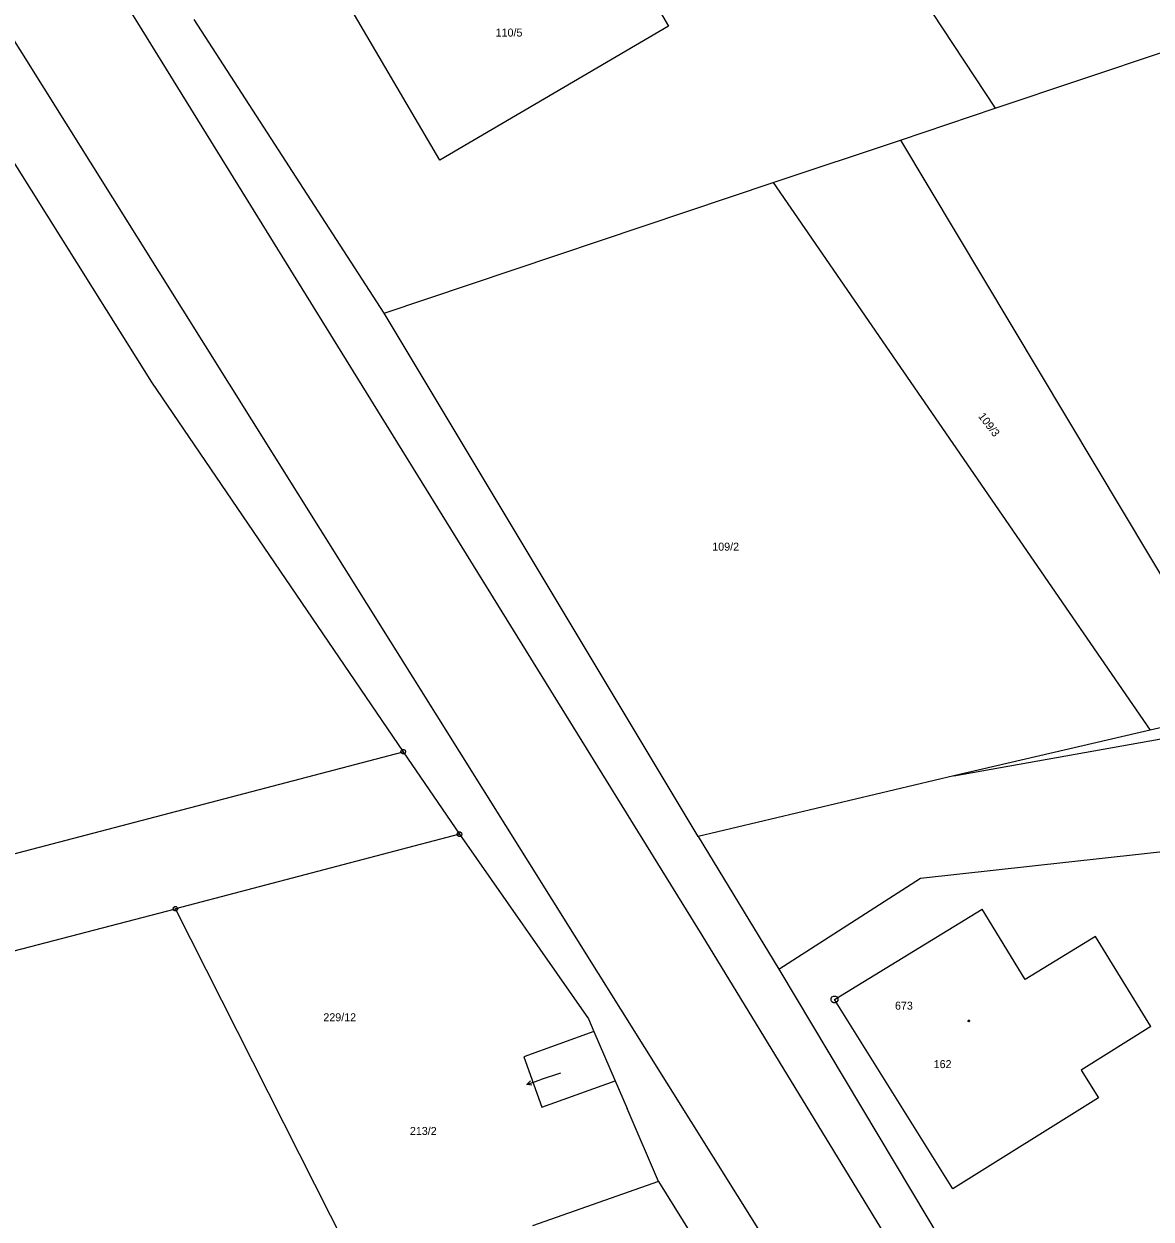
# Model space of a CAD drawing. Extents: x -871430 to -870620, y -1010094 to -1009649.
# Drawn here: x -871056.6 to -870996.8, y -1009857 to -1009793.5 of the extents above; entities that cross this region are included whole.
import ezdxf

# ---------------------------------------------------------------- set-up
doc = ezdxf.new("R2010")
doc.units = 0
for name, color, linetype in [('Vrstva 1', 7, 'Continuous'), ('Vrstva 2', 7, 'Continuous'), ('Vrstva 4', 7, 'Continuous'), ('Vrstva 5', 7, 'Continuous'), ('Vrstva 7', 7, 'Continuous'), ('Vrstva 8', 7, 'Continuous')]:
    doc.layers.add(name, color=color, linetype=linetype)

msp = doc.modelspace()

# ---------------------------------------------------------------- linework, layer by layer
at = {"layer": 'Vrstva 1'}
for p, q in [((-871019.06, -1009776.69), (-871005.04, -1009798.01)), ((-871037.49, -1009808.89), (-871047.58, -1009793.3)), ((-871005.04, -1009798.01), (-870995.93, -1009794.96)), ((-871010.06, -1009799.7), (-871005.04, -1009798.01)), ((-871057.82, -1009799.84), (-871049.86, -1009812.56)), ((-871016.82, -1009801.96), (-871010.06, -1009799.7)), ((-871010.06, -1009799.7), (-870991.98, -1009829.94)), ((-871037.49, -1009808.89), (-871016.82, -1009801.96)), ((-871016.82, -1009801.96), (-870996.8, -1009831.05)), ((-871020.82, -1009836.7), (-871037.49, -1009808.89)), ((-871049.86, -1009812.56), (-871036.48, -1009832.19)), ((-870991.98, -1009829.94), (-870996.8, -1009831.05)), ((-871007.23, -1009833.47), (-870991.55, -1009830.67)), ((-870996.8, -1009831.05), (-871007.23, -1009833.47)), ((-871091.79, -1009846.7), (-871036.48, -1009832.19)), ((-871036.48, -1009832.19), (-871033.49, -1009836.57)), ((-871007.23, -1009833.47), (-871020.82, -1009836.7)), ((-871033.49, -1009836.57), (-871048.58, -1009840.53)), ((-871033.49, -1009836.57), (-871026.64, -1009846.38)), ((-871020.82, -1009836.7), (-871016.52, -1009843.75)), ((-871009.01, -1009838.9), (-870993.95, -1009837.25)), ((-871016.52, -1009843.75), (-871009.01, -1009838.9)), ((-871131.99, -1009862.23), (-871048.58, -1009840.53)), ((-871038.84, -1009859.8), (-871048.58, -1009840.53)), ((-871013.57, -1009845.35), (-871005.72, -1009840.56)), ((-871003.45, -1009844.29), (-871005.72, -1009840.56)), ((-870999.7, -1009842), (-871003.45, -1009844.29)), ((-870996.77, -1009846.79), (-870999.7, -1009842)), ((-871016.52, -1009843.75), (-871002.66, -1009866.96)), ((-871007.28, -1009855.41), (-871013.57, -1009845.35)), ((-871026.64, -1009846.38), (-871026.35, -1009847.05)), ((-870996.77, -1009846.79), (-871000.47, -1009849.1)), ((-871026.35, -1009847.05), (-871030.08, -1009848.4)), ((-871026.35, -1009847.05), (-871025.22, -1009849.67)), ((-871030.08, -1009848.4), (-871029.11, -1009851.08)), ((-871000.47, -1009849.1), (-870999.55, -1009850.58)), ((-871029.11, -1009851.08), (-871025.22, -1009849.67)), ((-871025.22, -1009849.67), (-871024.58, -1009851.15)), ((-870999.55, -1009850.58), (-871007.28, -1009855.41)), ((-871022.92, -1009855.02), (-871024.58, -1009851.15)), ((-871022.92, -1009855.02), (-871029.61, -1009857.37)), ((-871022.92, -1009855.02), (-871009.29, -1009876.82))]:
    msp.add_line(p, q, dxfattribs=at)
msp.add_lwpolyline([(-871039.55, -1009792.22), (-871027.38, -1009785.1), (-871022.38, -1009793.65), (-871034.54, -1009800.76), (-871039.55, -1009792.22)], dxfattribs=at)
at = {"layer": 'Vrstva 4'}
for p, q in [((-871086.33, -1009747.82), (-871017.56, -1009857.66)), ((-871020.6, -1009841.94), (-871072.78, -1009757.54)), ((-870955.86, -1009947.84), (-871020.6, -1009841.94))]:
    msp.add_line(p, q, dxfattribs=at)
at = {"layer": 'Vrstva 5'}
msp.add_lwpolyline([(-871006.44, -1009846.448), (-871006.415, -1009846.452), (-871006.402, -1009846.475), (-871006.398, -1009846.49), (-871006.402, -1009846.512), (-871006.422, -1009846.53), (-871006.44, -1009846.532), (-871006.462, -1009846.525), (-871006.477, -1009846.51), (-871006.482, -1009846.49), (-871006.477, -1009846.468), (-871006.457, -1009846.45), (-871006.44, -1009846.448)], dxfattribs=at)
at = {"layer": 'Vrstva 7'}
for p in [(-871028.12, -1009849.26), (-871029.92, -1009849.872)]:
    msp.add_line(p, (-871029.21, -1009849.63), dxfattribs=at)
msp.add_lwpolyline([(-871029.643, -1009849.91), (-871029.92, -1009849.872), (-871029.724, -1009849.673)], dxfattribs=at)
at = {"layer": 'Vrstva 8'}
for p, q in [((-871036.492, -1009832.19), (-871036.468, -1009832.19)), ((-871033.502, -1009836.57), (-871033.478, -1009836.57)), ((-871048.592, -1009840.53), (-871048.568, -1009840.53)), ((-871013.582, -1009845.35), (-871013.558, -1009845.35))]:
    msp.add_line(p, q, dxfattribs=at)
for points in [[(-871036.442, -1009832.07), (-871036.38, -1009832.117), (-871036.355, -1009832.19), (-871036.38, -1009832.262), (-871036.442, -1009832.31), (-871036.518, -1009832.31), (-871036.58, -1009832.262), (-871036.605, -1009832.19), (-871036.58, -1009832.117), (-871036.518, -1009832.07), (-871036.442, -1009832.07)], [(-871033.452, -1009836.45), (-871033.39, -1009836.497), (-871033.365, -1009836.57), (-871033.39, -1009836.642), (-871033.452, -1009836.69), (-871033.528, -1009836.69), (-871033.59, -1009836.642), (-871033.615, -1009836.57), (-871033.59, -1009836.497), (-871033.528, -1009836.45), (-871033.452, -1009836.45)], [(-871048.542, -1009840.41), (-871048.48, -1009840.458), (-871048.455, -1009840.53), (-871048.48, -1009840.602), (-871048.542, -1009840.65), (-871048.617, -1009840.65), (-871048.68, -1009840.602), (-871048.705, -1009840.53), (-871048.68, -1009840.458), (-871048.617, -1009840.41), (-871048.542, -1009840.41)], [(-871013.522, -1009845.17), (-871013.438, -1009845.218), (-871013.39, -1009845.302), (-871013.39, -1009845.4), (-871013.438, -1009845.485), (-871013.522, -1009845.532), (-871013.62, -1009845.532), (-871013.705, -1009845.485), (-871013.752, -1009845.4), (-871013.752, -1009845.302), (-871013.705, -1009845.218), (-871013.62, -1009845.17), (-871013.522, -1009845.17)]]:
    msp.add_lwpolyline(points, dxfattribs=at)

# ---------------------------------------------------------------- texts
at = {"layer": 'Vrstva 2'}
for s, height, p in [('110/5', 0.425, (-871031.571, -1009794.2)), ('109/2', 0.425, (-871020.062, -1009821.51)), ('229/12', 0.425, (-871040.721, -1009846.51)), ('162', 0.425, (-871008.302, -1009849)), ('213/2', 0.025, (-871028.172, -1009849.26))]:
    msp.add_text(s, height=height, dxfattribs=at).set_placement(p)
msp.add_text('109/3', height=0.425, rotation=307.62104, dxfattribs=at).set_placement((-871005.96, -1009814.378))
at = {"layer": 'Vrstva 7'}
msp.add_text('213/2', height=0.425, dxfattribs=at).set_placement((-871036.125, -1009852.55))
at = {"layer": 'Vrstva 8'}
msp.add_text('673', height=0.425, dxfattribs=at).set_placement((-871010.357, -1009845.893))

doc.saveas('drawing.dxf')
